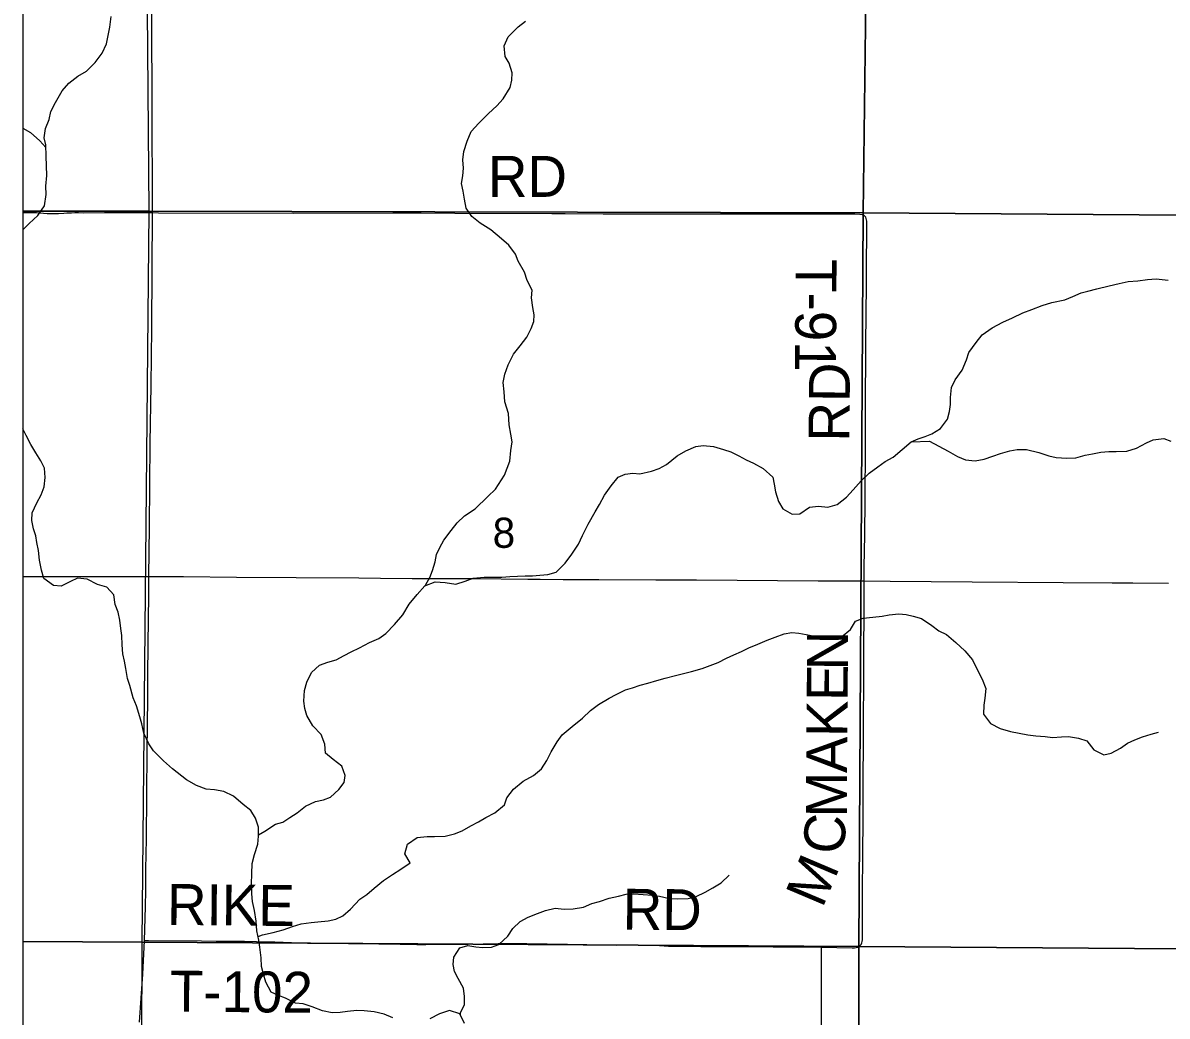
# Model space of a CAD drawing. Extents: x -87 to 2145, y -2128 to 440.
# Drawn here: x -47.037 to -45.448, y -695.2 to -693.821 of the extents above; entities that cross this region are included whole.
import ezdxf

# ---------------------------------------------------------------- set-up
doc = ezdxf.new("R2010")
doc.units = 0
for name, color, linetype in [('GM_X_Minor_River', 7, 'Continuous'), ('GM_X_Section', 7, 'Continuous'), ('GM_X_Section_Text', 7, 'Continuous'), ('GM_X_State_Route', 7, 'Continuous'), ('GM_X_Township_Road', 7, 'Continuous'), ('GM_X_Township_Road_Text', 7, 'Continuous'), ('GM_X_Township_Text', 7, 'Continuous'), ('SH_Cut_Line', 7, 'Continuous'), ('SN_P_Text', 7, 'Continuous')]:
    doc.layers.add(name, color=color, linetype=linetype)

msp = doc.modelspace()

# ---------------------------------------------------------------- linework, layer by layer
at = {"layer": 'GM_X_Minor_River'}
for points in [[(-47.0365, -694.1084), (-47.0278, -694.0995), (-47.0157, -694.0884), (-47.0067, -694.0749), (-47.004, -694.0594), (-47.0045, -694.0476), (-47.0031, -694.0328), (-47.0039, -694.0194), (-47.004, -694.0058), (-47.0048, -693.9902), (-47.0069, -693.9806), (-47.0051, -693.9677), (-47.0002, -693.9553), (-46.9977, -693.944), (-46.9913, -693.9316), (-46.9822, -693.9151), (-46.9728, -693.9047), (-46.9604, -693.8951), (-46.9481, -693.8878), (-46.9364, -693.8759), (-46.9266, -693.8628), (-46.9206, -693.8501), (-46.9181, -693.8387), (-46.9159, -693.827), (-46.914, -693.8119)], [(-46.4783, -694.6027), (-46.4773, -694.6009), (-46.4714, -694.5911), (-46.4681, -694.5813), (-46.4641, -694.5692), (-46.4623, -694.5589), (-46.4579, -694.5491), (-46.4524, -694.5393), (-46.4422, -694.5258), (-46.4335, -694.515), (-46.4234, -694.5053), (-46.4087, -694.4957), (-46.3909, -694.4786), (-46.3807, -694.4682), (-46.3681, -694.4491), (-46.3641, -694.4393), (-46.3608, -694.4294), (-46.359, -694.4146), (-46.3572, -694.4025), (-46.3593, -694.3918), (-46.3613, -694.3788), (-46.3624, -694.3635), (-46.3674, -694.347), (-46.3683, -694.3333), (-46.3699, -694.3203), (-46.3677, -694.3086), (-46.3629, -694.2958), (-46.3553, -694.2807), (-46.3463, -694.2695), (-46.3369, -694.2572), (-46.3309, -694.2455), (-46.3273, -694.2357), (-46.3267, -694.2262), (-46.3288, -694.2163), (-46.3304, -694.2029), (-46.3297, -694.1919), (-46.3363, -694.1788), (-46.3402, -694.167), (-46.349, -694.1516), (-46.3526, -694.142), (-46.3619, -694.1296), (-46.372, -694.1206), (-46.387, -694.1085), (-46.4016, -694.099), (-46.4132, -694.09), (-46.4213, -694.078), (-46.4233, -694.0658), (-46.4254, -694.0548), (-46.4278, -694.0441), (-46.4257, -694.0331), (-46.4251, -694.0225), (-46.4259, -694.0111), (-46.4246, -693.9997), (-46.4197, -693.9854), (-46.4144, -693.9718), (-46.4035, -693.9603), (-46.3903, -693.947), (-46.3786, -693.9362), (-46.3696, -693.9262), (-46.3601, -693.9109), (-46.3576, -693.9003), (-46.3574, -693.8905), (-46.3613, -693.8771), (-46.3672, -693.8675), (-46.3684, -693.853), (-46.3628, -693.8403), (-46.3491, -693.8266), (-46.339, -693.8185)], [(-47.0365, -693.9673), (-47.0261, -693.973), (-47.0131, -693.9846), (-47.0046, -693.9941)], [(-45.8034, -694.4028), (-45.7938, -694.3985), (-45.7842, -694.3953), (-45.7746, -694.3917), (-45.7626, -694.384), (-45.7532, -694.3713), (-45.7503, -694.3607), (-45.7489, -694.3508), (-45.7491, -694.3409), (-45.7473, -694.3273), (-45.7425, -694.3164), (-45.7327, -694.3029), (-45.7266, -694.2886), (-45.7234, -694.2784), (-45.7132, -694.2646), (-45.7049, -694.2542), (-45.691, -694.2443), (-45.6764, -694.2366), (-45.6629, -694.2305), (-45.6486, -694.2236), (-45.636, -694.219), (-45.6214, -694.2133), (-45.6083, -694.2094), (-45.5903, -694.2057), (-45.5792, -694.201), (-45.5677, -694.1959), (-45.5581, -694.1935), (-45.5458, -694.19), (-45.5286, -694.1859), (-45.5148, -694.1828), (-45.5022, -694.1801), (-45.4888, -694.1793), (-45.4755, -694.1773), (-45.4632, -694.1765), (-45.4465, -694.1784)], [(-46.5231, -695.2024), (-46.5352, -695.1972), (-46.5489, -695.1942), (-46.5629, -695.1924), (-46.5728, -695.1922), (-46.5858, -695.1934), (-46.5961, -695.1947), (-46.6072, -695.1952), (-46.6208, -695.1926), (-46.6348, -695.187), (-46.6473, -695.1829), (-46.6583, -695.1819), (-46.6718, -695.1751), (-46.6817, -695.1714), (-46.6918, -695.1666), (-46.6992, -695.1527), (-46.7027, -695.1416), (-46.7052, -695.1312), (-46.7057, -695.119), (-46.7076, -695.1041), (-46.7089, -695.0945), (-46.7117, -695.0815), (-46.7129, -695.0681), (-46.7149, -695.0532), (-46.7177, -695.0409), (-46.7186, -695.0302), (-46.719, -695.0161), (-46.7187, -695.0023), (-46.7181, -694.9882), (-46.7151, -694.9757), (-46.7106, -694.9613), (-46.7096, -694.9503), (-46.7093, -694.9377), (-46.7136, -694.925), (-46.7199, -694.9146), (-46.7308, -694.9063), (-46.7442, -694.8946), (-46.7578, -694.8882), (-46.7707, -694.886), (-46.7821, -694.8849), (-46.7957, -694.8797), (-46.8092, -694.8721), (-46.8287, -694.8564), (-46.8414, -694.8455), (-46.8552, -694.8318), (-46.8615, -694.8218), (-46.8684, -694.8071), (-46.8715, -694.7941), (-46.8744, -694.7845), (-46.879, -694.7691), (-46.8833, -694.758), (-46.8879, -694.7411), (-46.8911, -694.7311), (-46.8938, -694.7173), (-46.8955, -694.707), (-46.8976, -694.697), (-46.8988, -694.6844), (-46.8993, -694.6714), (-46.9006, -694.6619), (-46.9019, -694.6504), (-46.9043, -694.6393), (-46.9083, -694.6285), (-46.9103, -694.6151), (-46.92, -694.6046), (-46.9328, -694.6009), (-46.9471, -694.5933), (-46.9608, -694.5919), (-46.9704, -694.5966), (-46.9832, -694.6032), (-46.9942, -694.6022), (-47.0073, -694.5924), (-47.0105, -694.5809), (-47.0136, -694.5667), (-47.0148, -694.5533), (-47.0173, -694.5426), (-47.0186, -694.533), (-47.0218, -694.5234), (-47.0242, -694.512), (-47.0236, -694.5013), (-47.0172, -694.4873), (-47.0112, -694.476), (-47.0072, -694.4651), (-47.0058, -694.4522), (-47.0066, -694.4392), (-47.0114, -694.4292), (-47.0187, -694.418), (-47.0257, -694.4064), (-47.0319, -694.3937), (-47.0365, -694.3845)], [(-46.7096, -694.9484), (-46.7007, -694.9432), (-46.686, -694.9336), (-46.6757, -694.9308), (-46.666, -694.9242), (-46.656, -694.9175), (-46.644, -694.9086), (-46.6305, -694.9021), (-46.6194, -694.8996), (-46.6094, -694.8961), (-46.5981, -694.8852), (-46.5907, -694.8755), (-46.589, -694.866), (-46.5936, -694.8529), (-46.606, -694.8435), (-46.6165, -694.8349), (-46.6173, -694.8226), (-46.6224, -694.8088), (-46.6339, -694.7971), (-46.6424, -694.7828), (-46.6452, -694.7728), (-46.6465, -694.7629), (-46.6458, -694.748), (-46.6425, -694.7363), (-46.6357, -694.7231), (-46.6249, -694.7127), (-46.613, -694.7087), (-46.6018, -694.7052), (-46.5907, -694.6993), (-46.5807, -694.6942), (-46.5691, -694.6884), (-46.5552, -694.6811), (-46.5425, -694.6756), (-46.5329, -694.6686), (-46.5208, -694.6563), (-46.5091, -694.6428), (-46.5004, -694.6282), (-46.4894, -694.6147), (-46.4785, -694.6027), (-46.4643, -694.597), (-46.4502, -694.5981), (-46.4354, -694.6003), (-46.4227, -694.596), (-46.4116, -694.5921), (-46.3963, -694.5905), (-46.3861, -694.5907), (-46.3716, -694.5907), (-46.3605, -694.5894), (-46.3498, -694.5889), (-46.3392, -694.5888), (-46.3293, -694.5886), (-46.319, -694.5877), (-46.3079, -694.5868), (-46.2964, -694.5836), (-46.2839, -694.571), (-46.2745, -694.5586), (-46.2651, -694.5447), (-46.2595, -694.5327), (-46.2519, -694.5169), (-46.242, -694.4996), (-46.2361, -694.4898), (-46.2293, -694.4766), (-46.2199, -694.4635), (-46.2101, -694.4516), (-46.2005, -694.4476), (-46.1898, -694.4463), (-46.1799, -694.4469), (-46.1638, -694.4435), (-46.1535, -694.4395), (-46.1431, -694.4341), (-46.1283, -694.4222), (-46.1164, -694.4149), (-46.1025, -694.4091), (-46.0922, -694.4078), (-46.0778, -694.4089), (-46.0642, -694.4134), (-46.0536, -694.4163), (-46.0426, -694.4219), (-46.0325, -694.4275), (-46.0223, -694.4323), (-46.0087, -694.4398), (-45.9957, -694.4519), (-45.9936, -694.4615), (-45.9916, -694.4722), (-45.9877, -694.4856), (-45.9814, -694.4957), (-45.9686, -694.5032), (-45.9579, -694.5027), (-45.9448, -694.4935), (-45.9322, -694.4919), (-45.9193, -694.4933), (-45.9062, -694.4894), (-45.8931, -694.4795), (-45.8841, -694.4694), (-45.8731, -694.4567), (-45.8619, -694.4459), (-45.8499, -694.4375), (-45.8394, -694.4297), (-45.8286, -694.4239), (-45.8158, -694.4135), (-45.8034, -694.4028)], [(-45.8034, -694.4028), (-45.7779, -694.4015), (-45.7651, -694.4087), (-45.7523, -694.4154), (-45.7391, -694.423), (-45.7281, -694.4274), (-45.7148, -694.4289), (-45.7022, -694.4269), (-45.69, -694.4226), (-45.6796, -694.419), (-45.6666, -694.4152), (-45.6562, -694.4131), (-45.6433, -694.4131), (-45.6262, -694.4173), (-45.6122, -694.4222), (-45.602, -694.4243), (-45.5876, -694.4254), (-45.575, -694.425), (-45.5619, -694.4211), (-45.5516, -694.4191), (-45.5401, -694.4171), (-45.5291, -694.4162), (-45.5188, -694.416), (-45.5039, -694.4156), (-45.4909, -694.4114), (-45.477, -694.4041), (-45.4674, -694.3998), (-45.4529, -694.3982), (-45.4431, -694.4019)], [(-46.7101, -695.0892), (-46.7038, -695.087), (-46.6889, -695.0839), (-46.6751, -695.08), (-46.6621, -695.0753), (-46.6502, -695.0718), (-46.6364, -695.0702), (-46.6269, -695.0689), (-46.6128, -695.0676), (-46.602, -695.0652), (-46.5924, -695.0608), (-46.5819, -695.0515), (-46.5687, -695.0377), (-46.559, -695.0311), (-46.5489, -695.0225), (-46.5358, -695.0118), (-46.5234, -695.0033), (-46.5118, -694.9959), (-46.4987, -694.987), (-46.5064, -694.9746), (-46.5027, -694.961), (-46.4891, -694.9518), (-46.4754, -694.9505), (-46.4651, -694.9504), (-46.4503, -694.9503), (-46.4376, -694.9468), (-46.4269, -694.9425), (-46.4149, -694.9359), (-46.4041, -694.93), (-46.3937, -694.9242), (-46.3814, -694.9179), (-46.3682, -694.9068), (-46.3649, -694.897), (-46.3555, -694.885), (-46.3419, -694.8738), (-46.3277, -694.8661), (-46.3164, -694.8565), (-46.309, -694.8452), (-46.303, -694.8331), (-46.2951, -694.8192), (-46.288, -694.8095), (-46.274, -694.798), (-46.2597, -694.7861), (-46.2488, -694.7757), (-46.2376, -694.7672), (-46.2225, -694.7583), (-46.2129, -694.7532), (-46.2002, -694.747), (-46.1902, -694.7442), (-46.1795, -694.7406), (-46.1691, -694.7378), (-46.1565, -694.7339), (-46.145, -694.7308), (-46.1304, -694.7269), (-46.1082, -694.7213), (-46.0936, -694.7171), (-46.0825, -694.7131), (-46.0714, -694.7088), (-46.0598, -694.703), (-46.0498, -694.6983), (-46.039, -694.6936), (-46.029, -694.6888), (-46.0164, -694.6834), (-46.0033, -694.678), (-45.9921, -694.6737), (-45.9799, -694.6694), (-45.9692, -694.6673), (-45.9593, -694.6683), (-45.9494, -694.6701), (-45.9399, -694.6718), (-45.9263, -694.6748), (-45.9134, -694.6763), (-45.9, -694.6735), (-45.8879, -694.6631), (-45.8808, -694.6515), (-45.8701, -694.6475), (-45.8567, -694.6459), (-45.8437, -694.6447), (-45.8342, -694.6427), (-45.8204, -694.6415), (-45.8102, -694.6425), (-45.8007, -694.6446), (-45.789, -694.6479), (-45.7747, -694.6574), (-45.7649, -694.6648), (-45.7544, -694.67), (-45.7413, -694.6814), (-45.729, -694.6927), (-45.7182, -694.7055), (-45.7117, -694.7186), (-45.7051, -694.7321), (-45.7, -694.7452), (-45.7011, -694.7585), (-45.7028, -694.7684), (-45.7031, -694.7809), (-45.6935, -694.7937), (-45.6799, -694.8005), (-45.6655, -694.8047), (-45.6534, -694.8072), (-45.6416, -694.8094), (-45.6302, -694.8108)], [(-45.6302, -694.8108), (-45.6173, -694.8119), (-45.6074, -694.8129), (-45.5949, -694.812), (-45.5853, -694.8119), (-45.5713, -694.8141), (-45.5596, -694.8178), (-45.5499, -694.8302), (-45.536, -694.837), (-45.526, -694.835), (-45.5129, -694.828), (-45.5033, -694.821), (-45.4929, -694.8163), (-45.4825, -694.812), (-45.4702, -694.8085), (-45.4603, -694.8057)], [(-46.4289, -695.1993), (-46.4289, -695.1954), (-46.4237, -695.1836), (-46.4235, -695.1726), (-46.4247, -695.1611), (-46.4321, -695.1476), (-46.4376, -695.1379), (-46.4393, -695.1284), (-46.4383, -695.1181), (-46.43, -695.1053), (-46.4189, -695.1021), (-46.4079, -695.1039), (-46.398, -695.1049), (-46.3862, -695.104), (-46.3758, -695.1004), (-46.3634, -695.0889), (-46.3563, -695.0783), (-46.3462, -695.0686), (-46.335, -695.0624), (-46.3223, -695.0574), (-46.3112, -695.0534), (-46.2978, -695.0503), (-46.2852, -695.0513), (-46.2727, -695.0512), (-46.2585, -695.0489), (-46.2466, -695.0438), (-46.2363, -695.0406), (-46.2228, -695.0363), (-46.2098, -695.0332), (-46.1991, -695.0307), (-46.1888, -695.0302), (-46.1755, -695.0313), (-46.163, -695.0319), (-46.1527, -695.0333), (-46.1391, -695.0367), (-46.1273, -695.0373), (-46.1128, -695.0365), (-46.1021, -695.0341), (-46.0894, -695.0279), (-46.0789, -695.022), (-46.067, -695.015), (-46.0561, -695.0042)], [(-46.4235, -695.21), (-46.4301, -695.1969), (-46.4445, -695.1923), (-46.4583, -695.197), (-46.4717, -695.2036)]]:
    msp.add_lwpolyline(points, dxfattribs=at)
at = {"layer": 'GM_X_Section'}
for points in [[(-46.8694, -693.0773), (-46.8349, -693.0776), (-45.8577, -693.0847), (-45.8699, -694.0845), (-46.8611, -694.0824)], [(-45.8274, -693.0842), (-44.8494, -693.0853), (-44.8488, -694.0921), (-45.8699, -694.0845), (-45.8577, -693.0847)], [(-46.8611, -694.0824), (-45.8699, -694.0845), (-45.8763, -695.1033), (-46.8709, -695.0973)], [(-45.8699, -694.0845), (-44.8488, -694.0921), (-44.8557, -695.1105), (-45.8763, -695.1033)], [(-46.8709, -695.0973), (-45.8763, -695.1033), (-45.8769, -696.0942), (-46.8743, -696.1139)], [(-45.8763, -695.1033), (-44.8557, -695.1105), (-44.866, -696.0959), (-45.8769, -696.0942)]]:
    msp.add_lwpolyline(points, close=True, dxfattribs=at)
at = {"layer": 'GM_X_State_Route'}
for points in [[(-46.8615, -694.5896), (-46.8608, -694.5207), (-46.8598, -694.4039), (-46.8586, -694.3244), (-46.8576, -694.2449), (-46.8564, -694.0844), (-46.857, -693.9317), (-46.8573, -693.8217), (-46.8591, -693.5055)], [(-47.0365, -694.5894), (-47.0086, -694.5895), (-46.9496, -694.5894), (-46.8615, -694.5896)], [(-46.8748, -695.2082), (-46.87, -695.1419), (-46.8676, -695.095), (-46.8663, -695.0483), (-46.8659, -695.0252), (-46.8657, -694.9966), (-46.8648, -694.9538), (-46.8645, -694.8929), (-46.8639, -694.8326), (-46.8631, -694.7581), (-46.863, -694.727), (-46.8628, -694.6841), (-46.8616, -694.6152), (-46.8615, -694.5896)], [(-46.8615, -694.5896), (-46.8135, -694.5898), (-46.7402, -694.5905), (-46.657, -694.5911), (-46.57, -694.5916), (-46.5402, -694.5919), (-46.4961, -694.5922), (-46.4451, -694.5925), (-46.4103, -694.5926), (-46.3358, -694.5932), (-46.3184, -694.5934), (-46.2867, -694.5936), (-46.237, -694.5937), (-46.1581, -694.5942), (-46.1264, -694.5943), (-46.1016, -694.5944), (-45.9326, -694.5956), (-45.9046, -694.5956), (-45.8688, -694.5958), (-45.8326, -694.596), (-45.7189, -694.5971), (-45.5927, -694.5978), (-45.5244, -694.5982), (-45.4958, -694.5985), (-45.4461, -694.5988)]]:
    msp.add_lwpolyline(points, dxfattribs=at)
at = {"layer": 'GM_X_Township_Road'}
for points in [[(-47.0365, -694.084), (-47.0267, -694.084), (-47.0174, -694.0844), (-47.0026, -694.0854), (-46.997, -694.0857), (-46.9927, -694.0858), (-46.9872, -694.0855), (-46.9798, -694.085), (-46.9754, -694.0847), (-46.9692, -694.0845), (-46.9643, -694.0844), (-46.9593, -694.0844), (-46.9526, -694.0845), (-46.9234, -694.0843), (-46.8701, -694.0844), (-46.8564, -694.0844)], [(-46.8564, -694.0844), (-46.8484, -694.0845), (-46.6608, -694.0852), (-46.5229, -694.0849), (-46.4838, -694.0849), (-46.437, -694.0851), (-46.3024, -694.0857), (-46.2837, -694.0858), (-46.231, -694.086), (-46.1744, -694.0863), (-46.1235, -694.0862), (-46.0483, -694.0863), (-45.9682, -694.0863), (-45.8818, -694.0862), (-45.8749, -694.0864), (-45.8716, -694.087), (-45.8692, -694.0878), (-45.8676, -694.0891)], [(-45.8688, -694.5958), (-45.8688, -694.5901), (-45.8686, -694.5765), (-45.8677, -694.5317), (-45.8674, -694.4833), (-45.8675, -694.4672), (-45.8667, -694.4249), (-45.8668, -694.3691), (-45.8669, -694.3548), (-45.8663, -694.2722), (-45.8658, -694.22), (-45.8654, -694.1896), (-45.8653, -694.1672), (-45.8651, -694.1017), (-45.8652, -694.0963), (-45.8655, -694.0942), (-45.8658, -694.0925), (-45.8666, -694.0906), (-45.8676, -694.0891)], [(-45.9279, -695.1041), (-45.8853, -695.1053), (-45.8821, -695.1051), (-45.8796, -695.1048), (-45.8777, -695.1041), (-45.8759, -695.1032), (-45.8743, -695.1019), (-45.873, -695.1003), (-45.8721, -695.0984), (-45.8716, -695.0965), (-45.8711, -695.0941), (-45.8709, -695.0917), (-45.8708, -695.0889), (-45.8711, -695.0379), (-45.871, -695.0193), (-45.8707, -694.9864), (-45.8705, -694.9609), (-45.8702, -694.941), (-45.8699, -694.9006), (-45.8695, -694.7919), (-45.8694, -694.7336), (-45.8691, -694.6857), (-45.8686, -694.6454), (-45.8688, -694.6099), (-45.8688, -694.5958)], [(-46.8676, -695.095), (-46.8623, -695.095), (-46.7885, -695.0955), (-46.768, -695.0957), (-46.7568, -695.0957), (-46.7382, -695.0958), (-46.7289, -695.096), (-46.7121, -695.0963), (-46.6866, -695.0969), (-46.6637, -695.0976), (-46.5847, -695.0991), (-46.5425, -695.0998), (-46.5127, -695.1002), (-46.4897, -695.1004), (-46.4772, -695.1003), (-46.4182, -695.0999), (-46.3766, -695.0993), (-46.3629, -695.0991), (-46.3512, -695.0992), (-46.337, -695.0993), (-46.2806, -695.1002), (-46.2266, -695.101), (-46.2129, -695.1014), (-46.1999, -695.1012), (-46.1527, -695.102), (-46.1403, -695.1026), (-46.1248, -695.1028), (-46.0956, -695.1032), (-46.0626, -695.1034), (-45.9279, -695.1041)], [(-45.9127, -695.6016), (-45.9133, -695.5954), (-45.9149, -695.58), (-45.9209, -695.5194), (-45.9256, -695.4687), (-45.9266, -695.4551), (-45.9277, -695.4327), (-45.928, -695.4166), (-45.9278, -695.3154), (-45.928, -695.2477), (-45.928, -695.188), (-45.9279, -695.1041)]]:
    msp.add_lwpolyline(points, dxfattribs=at)
at = {"layer": 'GM_X_Township_Text'}
msp.add_lwpolyline([(-47.0365, -692.0677), (-47.0365, -697.4226)], dxfattribs=at)
at = {"layer": 'SH_Cut_Line'}
msp.add_lwpolyline([(-47.0365, -692.0677), (-47.0365, -697.4226), (-40.2365, -697.4226), (-40.2365, -692.0607)], dxfattribs=at)
at = {"layer": 'SN_P_Text'}
for points in [[(-47.0365, -693.0764), (-47.0365, -694.0826), (-46.8611, -694.0824), (-46.8694, -693.0773)], [(-47.0365, -694.0826), (-47.0365, -695.0962), (-46.8709, -695.0973), (-46.8611, -694.0824)], [(-47.0365, -695.0962), (-47.0365, -696.1112), (-46.8743, -696.1139), (-46.8709, -695.0973)]]:
    msp.add_lwpolyline(points, close=True, dxfattribs=at)

# ---------------------------------------------------------------- texts
at = {"layer": 'GM_X_Section_Text'}
msp.add_text('8', height=0.0419, rotation=0, dxfattribs=at).set_placement((-46.3844, -694.5498))
at = {"layer": 'GM_X_Township_Road_Text'}
for s, height, rotation, p in [('RD', 0.05682, 0, (-46.391, -694.0625)), ('T-91', 0.05682, 269.6479, (-45.9638, -694.1488)), ('RD', 0.05682, 89.51, (-45.8892, -694.4025)), ('N', 0.0568, 89.5665, (-45.8914, -694.7201)), ('E', 0.0568, 89.5671, (-45.8917, -694.7626)), ('K', 0.0568, 89.5647, (-45.8921, -694.8126)), ('A', 0.0568, 89.5665, (-45.8924, -694.8626)), ('M', 0.0568, 89.7118, (-45.8928, -694.9242)), ('C', 0.0568, 83.8022, (-45.8982, -694.977)), ('M', 0.0568, 67.0314, (-45.9268, -695.0513)), ('RIKE', 0.05682, 359.4177, (-46.8367, -695.0732)), ('RD', 0.05682, 359.511, (-46.2041, -695.0799)), ('T-102', 0.05682, 359.4452, (-46.8327, -695.1935))]:
    msp.add_text(s, height=height, rotation=rotation, dxfattribs=at).set_placement(p)

doc.saveas('drawing.dxf')
